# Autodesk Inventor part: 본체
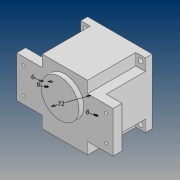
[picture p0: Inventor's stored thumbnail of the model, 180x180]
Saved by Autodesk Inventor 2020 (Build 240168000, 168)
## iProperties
Created: 2020-07
Part Number: 본체
Material: 일반
Document SubType Name: Modeling
Designer: PC312-
Density: 1 g/cm^3
Appearance: 기본값
Author: PC312-
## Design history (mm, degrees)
sketch "스케치1"
  geometry: L1 (-47, 47)-(47, 47); L2 (47, 47)-(47, -47); L3 (47, -47)-(-47, -47); L4 (-47, -47)-(-47, 47); L5 (-47, 47)-(47, -47); L6 (47, 47)-(-47, -47); 1 further point
  constraints: 12 end point, 2 midpoint, 2 parallel, 1 horizontal, 1 perpendicular
  dimensions: "d0" = 94 distance of L2.end L3.end; "d1" = 94 distance of L1.end L2.end
extrude "돌출1" new body sketch "스케치1" stored distance "d2" = 80; taper "d3" = 0 deg
sketch "스케치2"
  geometry: C1 r 27.5 at (0, 11); 1 further point
  constraints: 1 centre point, 1 vertical alignment
  dimensions: "d4" = 55 diameter of C1; "d5" = 11 distance of point (0, 0) C1.centre
extrude "돌출2" join sketch "스케치2" distance "d6" = 7; taper "d7" = 0 deg
sketch "스케치3"
  geometry: L1 (-70, 30)-(70, 30); L2 (70, 30)-(70, -30); L3 (70, -30)-(-70, -30); L4 (-70, -30)-(-70, 30); L5 (-70, 30)-(70, -30); L6 (70, 30)-(-70, -30); 1 further point
  constraints: 12 end point, 2 midpoint, 2 parallel, 1 horizontal, 1 perpendicular
  dimensions: "d8" = 140 distance of L2.end L3.end; "d9" = 60 distance of L1.end L2.end
extrude "돌출3" join sketch "스케치3" distance "d10" = 13; taper "d11" = 0 deg
sketch "스케치4"
  geometry: L1 (47, 47)-(-47, 47) reference; L2 (33, 47)-(33, 30); L3 (47, 30)-(47, -30) reference; L4 (33, 30)-(47, 30); L5 (47, 30)-(47, 47) reference; L6 (33, 47)-(47, 47); L7 (47, 47)-(47, 29.432); 1 further point
  constraints: 8 end point, 2 point on line, 1 horizontal, 1 vertical
  dimensions: "d12" = 17 distance of L2.start L2.end; "d14" = 14 distance of L2.end L3.start
extrude "돌출4" cut sketch "스케치4" distance "d15" = 70; taper "d16" = 0 deg
sketch "스케치5"
  geometry: C1 r 3.5 at (-40, -40); C2 r 3.5 at (40, -40); C3 r 3.5 at (-40, 40); C4 r 3.5 at (40, 40); 1 further point
  constraints: 4 centre point
  dimensions: "d17" = 7 diameter of C1; "d18" = 7 diameter of C2; "d19" = 7 diameter of C3; "d20" = 7 diameter of C4; "d21" = 80 distance of C2.centre C4.centre; "d22" = 80 distance of C1.centre C3.centre; "d23" = 80 distance of C4.centre C3.centre; "d24" = 80 distance of C2.centre C1.centre; "d25" = 40 horizontal distance of C4.centre point (0, 0); "d26" = 40 horizontal distance of point (0, 0) C3.centre; "d27" = 40 horizontal distance of C2.centre point (0, 0); "d28" = 40 horizontal distance of C2.centre point (0, 0)
extrude "돌출5" cut sketch "스케치5" extent not by distance; stored distance "d29" = 0; taper "d30" = 0 deg
sketch "스케치6"
  geometry: 3 further points
  constraints: 1 vertical alignment
  dimensions: "d31" = 38 distance of point (-60, 19) point (-60, -19); "d32" = 19 vertical distance of point (-60, -19) point (0, 0); "d33" = 60 horizontal distance of point (-60, -19) point (0, 0)
hole "구멍1" sketch "스케치6" at (-60, -19), (-60, 19) diameter "d34" = 4.5; stored, may be unused: countersink angle "d38" = 90 deg, drill point angle "d40" = 118 deg; dims "d35" = 8, "d36" = 10, "d37" = 5, "d39" = 13
sketch "스케치7"
  geometry: C1 r 43 at (0, 0); 1 further point
  constraints: 1 centre point, 1 coincident
  dimensions: "d41" = 86 diameter of C1
extrude "돌출6" cut sketch "스케치7" distance "d42" = 9; taper "d43" = 0 deg
sketch "스케치8"
  geometry: C1 r 40 at (0, 0); 1 further point
  constraints: 1 centre point, 1 coincident
  dimensions: "d44" = 80 diameter of C1
extrude "돌출7" cut sketch "스케치8" distance "d45" = 62; taper "d46" = 0 deg
sketch "스케치9"
  geometry: A1 r 21 centre (0, 11) between (12.163, -6.119) and (-12.163, -6.119); A2 r 15 centre (0, -20) between (-11.584, -10.47) and (11.584, -10.47); A3 r 3 centre (-13.901, -8.565) between (-11.584, -10.47) and (-12.163, -6.119); A4 r 3 centre (13.901, -8.565) between (12.163, -6.119) and (11.584, -10.47); 1 further point
  constraints: 8 point on circle, 4 centre point, 4 tangent, 2 vertical alignment
  dimensions: "d47" = 42 diameter of A1; "d48" = 30 diameter of A2; "d49" = 11 distance of point (0, 0) A1.centre; "d50" = 20 distance of point (0, 0) A2.centre; "d51" = 6 diameter of A3; "d52" = 6 diameter of A4
extrude "돌출8" join sketch "스케치9" distance "d53" = 7; taper "d54" = 0 deg
sketch "스케치10"
  geometry: C1 r 4 at (36, 0); C2 r 4 at (-36, 0); C3 r 3 at (36.762, 6.342); A1 r 36 centre (0, 0) between (36, 0) and (-36, 0); 1 further point
  constraints: 4 centre point, 2 horizontal alignment, 2 point on circle, 1 coincident
  dimensions: "d55" = 72 diameter of A1; "d56" = 8 diameter of C1; "d57" = 8 diameter of C2; "d58" = 6 diameter of C3
node "솔리드1"
mirror "미러1"
mirror "미러2"
mirror "미러3"
feature "A9D066F2-1C7D-4E18-AEED-F7BC21143FA4" dims "d34" = 4.5, "d35" = 8, "d36" = 10, "d37" = 5, "d38" = 90 deg, "d39" = 13, "d40" = 118 deg
